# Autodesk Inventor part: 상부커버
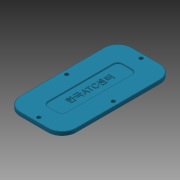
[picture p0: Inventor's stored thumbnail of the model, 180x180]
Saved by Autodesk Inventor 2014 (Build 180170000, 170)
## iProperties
Created: 2016-02
Part Number: 상부커버
Material: 강철, 연강
Document SubType Name: Modeling
Designer: mduedu
Density: 1 g/cm^3
Mass: 15.5198 g
Surface Area: 149.263 cm^2
Volume: 15.5198 cm^3
Appearance: 터키옥색
Author: mduedu
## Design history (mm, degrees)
sketch "스케치1"
  geometry: L1 (30, 60)-(-30, 60); L2 (-30, 60)-(-30, -60); L3 (-30, -60)-(30, -60); L4 (30, -60)-(30, 60); L5 (30, 60)-(-30, -60); L6 (-30, 60)-(30, -60); 1 further point
  constraints: 12 end point, 2 midpoint, 2 parallel, 1 horizontal, 1 perpendicular
  dimensions: "d0" = 60 distance of L2.end L3.end; "d2" = 120 distance of L1.end L2.end
extrude "돌출1" new body sketch "스케치1" distance "d3" = 4; taper "d4" = 0 deg
fillet "모깎기1" dims "d5" = 15
sketch "스케치2"
  geometry: L1 (30, 45)-(30, -45) reference; L2 (15, -60)-(-15, -60) reference; L3 (-30, -45)-(-30, 45) reference; L4 (-15, 60)-(15, 60) reference; L5 (25, 45)-(25, -45); L6 (15, -55)-(-15, -55); L7 (-25, -45)-(-25, 45); L8 (-15, 55)-(15, 55); A1 r 15 centre (15, 45) between (30, 45) and (15, 60) reference; A2 r 15 centre (15, -45) between (15, -60) and (30, -45) reference; A3 r 15 centre (-15, -45) between (-30, -45) and (-15, -60) reference; A4 r 15 centre (-15, 45) between (-15, 60) and (-30, 45) reference; A5 r 10 centre (15, 45) between (25, 45) and (15, 55); A6 r 10 centre (15, -45) between (15, -55) and (25, -45); A7 r 10 centre (-15, -45) between (-25, -45) and (-15, -55); A8 r 10 centre (-15, 45) between (-15, 55) and (-25, 45); 4 further points
  constraints: 8 end point, 8 point on circle, 4 centre point, 4 midpoint, 7 other
  dimensions: "d8" = 5 distance between parallel lines of L7 L3
hole "구멍1" sketch "스케치2" at (0, 55), (25, 0), (0, -55), (-25, 0) diameter "d9" = 4; stored, may be unused: countersink angle "d13" = 90 deg, drill point angle "d15" = 118 deg; dims "d10" = 6, "d11" = 4, "d12" = 2, "d14" = 8
sketch "스케치3"
  geometry: L1 (10, -40)-(-10, -40); L2 (-10, -40)-(-10, 40); L3 (-10, 40)-(10, 40); L4 (10, 40)-(10, -40); L5 (10, -40)-(-10, 40); L6 (-10, -40)-(10, 40); 1 further point
  constraints: 12 end point, 2 midpoint, 2 parallel, 1 horizontal, 1 perpendicular
  dimensions: "d16" = 80 distance of L1.end L2.end; "d18" = 20 distance of L2.end L3.end
extrude "돌출2" cut sketch "스케치3" distance "d19" = 1; taper "d20" = 0 deg
fillet "모깎기2" dims "d21" = 5
fillet "모깎기3" dims "d22" = 0.3
fillet "모깎기4" dims "d23" = 0.3
sketch "스케치4"
  geometry: 2 further points
  constraints: 1 coincident, 1 other
feature "엠보싱1" sketch "스케치4" dims "d0" = 60, "d2" = 120, "d11" = 4, "d24" = 0.5, "d25" = 0
node "솔리드1"
node "절단 모서리 투영1"
